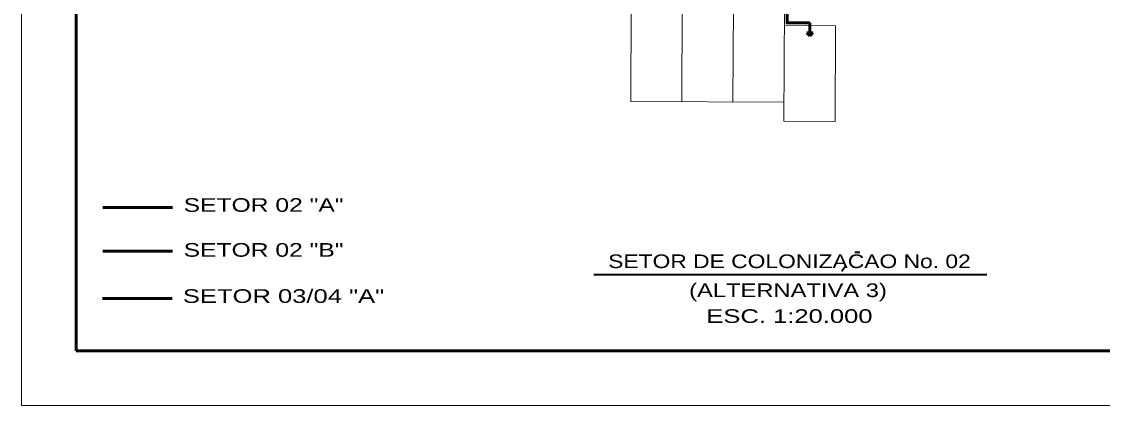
# Model space of a CAD drawing. Extents: x 312964 to 351929, y 9004151 to 9034973.
# Drawn here: x 335043 to 339002, y 9026327 to 9027732 of the extents above; entities that cross this region are included whole.
import ezdxf
from ezdxf.enums import TextEntityAlignment as Align

# ---------------------------------------------------------------- set-up
doc = ezdxf.new("R2010")
doc.units = 0
doc.header["$LTSCALE"] = 10
doc.layers.add('1', color=7, linetype='Continuous', lineweight=13)
doc.layers.add('2', color=7, linetype='Continuous', lineweight=53)

msp = doc.modelspace()

# ---------------------------------------------------------------- linework, layer by layer
at = {"layer": '1', "lineweight": 53}
for p, q in [((335242.63, 9030027), (335242.63, 9026527)), ((335339.58, 9027051.34), (335595.52, 9027051.34)), ((335339.58, 9026892.33), (335595.52, 9026892.33)), ((335338.39, 9026717.82), (335594.34, 9026717.82)), ((335242.63, 9026527), (340782.63, 9026527))]:
    msp.add_line(p, q, dxfattribs=at)
at = {"layer": '1'}
for p, q in [((337276.02, 9027790.07), (337274.7, 9027440.07)), ((337463.02, 9027789.36), (337461.69, 9027439.36)), ((337650.02, 9027788.65), (337648.69, 9027438.65)), ((337837.02, 9027787.94), (337835.43, 9027367.95)), ((337836.75, 9027717.94), (338023.75, 9027717.24)), ((338023.75, 9027717.24), (338022.43, 9027367.24)), ((337274.7, 9027440.07), (337835.69, 9027437.95)), ((337835.43, 9027367.95), (338022.43, 9027367.24))]:
    msp.add_line(p, q, dxfattribs=at)
at = {"layer": '1', "lineweight": 40}
for p, q in [((338095.6, 9026887.67), (338113.89, 9026887.67)), ((338060.7, 9026837.06), (338048.04, 9026817.35)), ((337138.64, 9026806.86), (338578.04, 9026806.86))]:
    msp.add_line(p, q, dxfattribs=at)
at = {"layer": '1'}
msp.add_lwpolyline([(335042.63, 9030527), (335042.63, 9026327), (340982.63, 9026327), (340982.63, 9030527)], dxfattribs=at)
at = {"layer": '2'}
for p, q in [((337930.14, 9027691.74), (337930.26, 9027727.59)), ((337919.62, 9027691.78), (337941.18, 9027691.71)), ((337930.36, 9027680.96), (337919.62, 9027691.78)), ((337930.36, 9027680.96), (337941.18, 9027691.71))]:
    msp.add_line(p, q, dxfattribs=at)
msp.add_lwpolyline([(337228.28, 9027800.25), (337588.28, 9027798.89), (337847.06, 9027797.91), (337846.79, 9027727.91), (337930.29, 9027727.59)], dxfattribs=at)

# ---------------------------------------------------------------- texts
at = {"layer": '1'}
for s, width, p in [('SETOR 02 "A"', 1.35, (335929.13, 9027035.83)), ('SETOR 02 "B"', 1.35, (335929.13, 9026871.34)), ('SETOR DE COLONIZACAO No. 02', 1.25, (337855.66, 9026829.73)), ('SETOR 03/04 "A"', 1.4, (336002.16, 9026702.31)), ('(ALTERNATIVA 3)', 1.3, (337850.22, 9026723.62)), ('ESC. 1:20.000', 1.4, (337855.47, 9026628.97))]:
    msp.add_text(s, height=50, dxfattribs=dict(at, width=width)).set_placement(p, align=Align.CENTER)

doc.saveas('drawing.dxf')
